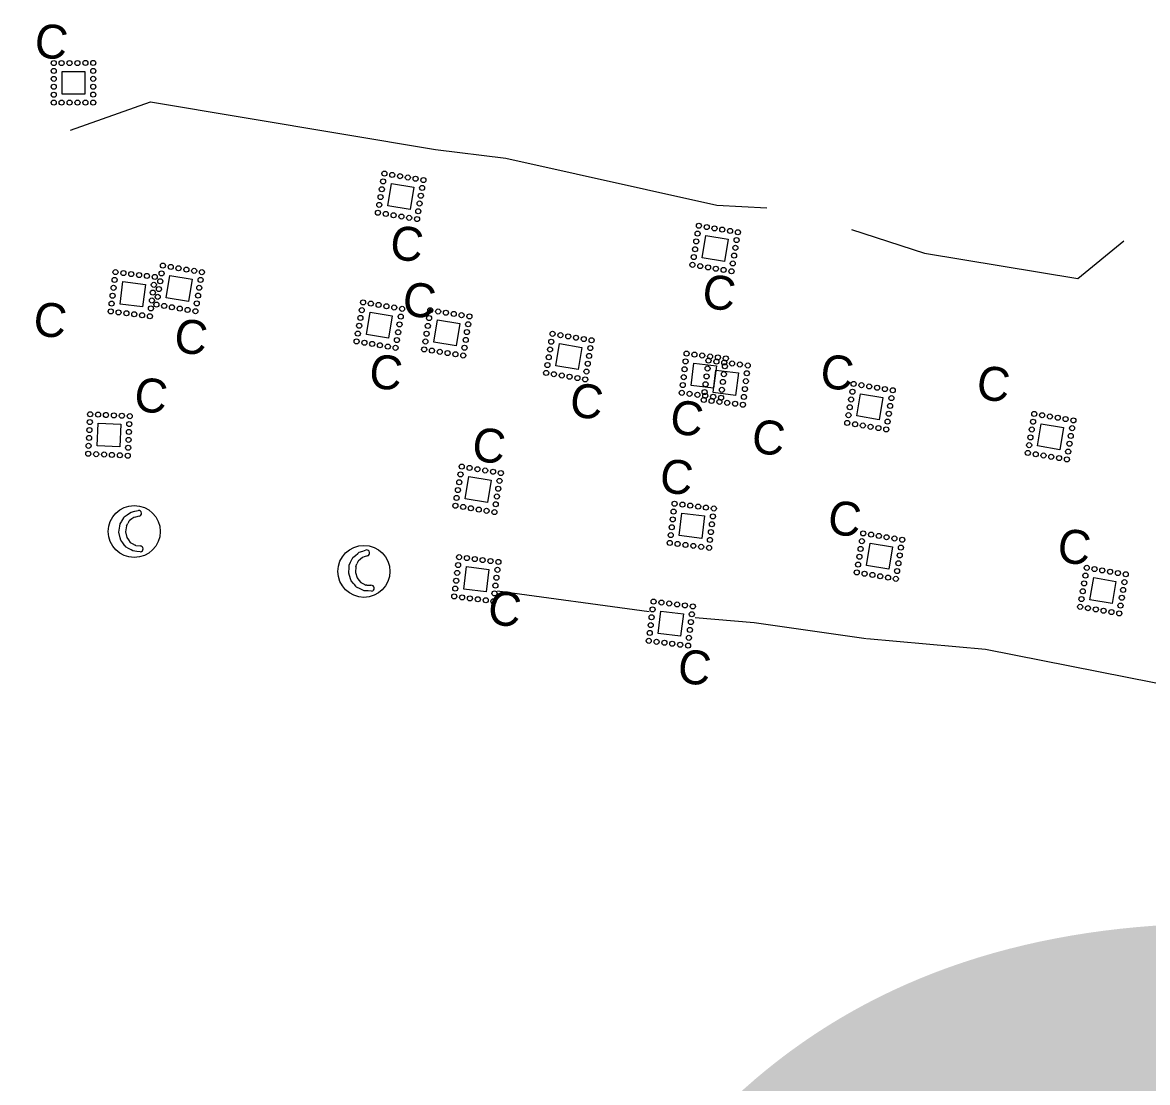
# Model space of a CAD drawing. Extents: x 2470000 to 2520000, y 340000 to 380000.
# Drawn here: x 2483983.6 to 2484481.2, y 365444.5 to 365913.2 of the extents above; entities that cross this region are included whole.
import ezdxf

# ---------------------------------------------------------------- set-up
doc = ezdxf.new("R2010")
doc.units = 0
for name, color, linetype in [('Coir Fiber Wattle with PAM Both CELL', 7, 'Continuous'), ('Prop Guardrail', 7, 'Continuous'), ('Prop Guardrail Anchor Unit CELL', 7, 'Continuous'), ('Prop Structure Anchor Unit CELL', 7, 'Continuous'), ('Rock Inlet Sediment Trap Type C CG CELL', 7, 'Continuous'), ('Scratch_Level_5', 7, 'Continuous'), ('Scratch_Level_6', 7, 'Continuous'), ('Sheet Data Field CELL', 7, 'Continuous')]:
    doc.layers.add(name, color=color, linetype=linetype)

# ---------------------------------------------------------------- blocks, each defined once
blk = doc.blocks.new('C3')
at = {"layer": 'Prop Guardrail'}
blk.add_text('C', height=0.3, dxfattribs=at).set_placement((-0.161, -0.136))
blk = doc.blocks.new('C2')
at = {"layer": 'Prop Guardrail Anchor Unit CELL'}
blk.add_text('C', height=0.3, dxfattribs=at).set_placement((-0.161, -0.136))

msp = doc.modelspace()

# ---------------------------------------------------------------- linework, layer by layer
at = {"layer": 'Coir Fiber Wattle with PAM Both CELL'}
for p, q in [((2484030.67, 365692.63), (2484030.13, 365691.66)), ((2484030.67, 365692.63), (2484030.79, 365692.84)), ((2484031.96, 365693.69), (2484030.79, 365692.84)), ((2484032.85, 365694.34), (2484031.96, 365693.69)), ((2484033.63, 365694.52), (2484032.85, 365694.34)), ((2484035.14, 365694.86), (2484033.63, 365694.52)), ((2484029.55, 365690.62), (2484029.21, 365688.01)), ((2484029.21, 365688), (2484029.21, 365688.01)), ((2484029.21, 365688), (2484029.75, 365685.52)), ((2484029.55, 365690.62), (2484030.13, 365691.66)), ((2484029.75, 365685.52), (2484030.43, 365684.53)), ((2484030.43, 365684.53), (2484031.25, 365683.33)), ((2484031.25, 365683.33), (2484032.13, 365682.82)), ((2484032.13, 365682.82), (2484033.41, 365682.07)), ((2484033.74, 365682.03), (2484033.41, 365682.07)), ((2484033.74, 365682.03), (2484035.58, 365681.76)), ((2484136.19, 365677.38), (2484134.71, 365676.91)), ((2484130.96, 365672.7), (2484130.83, 365670.08)), ((2484130.96, 365672.7), (2484131.46, 365673.79)), ((2484131.92, 365674.8), (2484131.46, 365673.79)), ((2484131.92, 365674.8), (2484132.02, 365675.01)), ((2484133.12, 365675.96), (2484132.02, 365675.01)), ((2484133.96, 365676.67), (2484133.12, 365675.96)), ((2484134.71, 365676.91), (2484133.96, 365676.67)), ((2484130.83, 365670.07), (2484130.83, 365670.08)), ((2484130.83, 365670.07), (2484131.57, 365667.63)), ((2484131.57, 365667.63), (2484132.32, 365666.7)), ((2484132.32, 365666.7), (2484133.24, 365665.58)), ((2484133.24, 365665.58), (2484134.16, 365665.13)), ((2484134.16, 365665.13), (2484135.5, 365664.49)), ((2484135.83, 365664.47), (2484135.5, 365664.49)), ((2484135.83, 365664.47), (2484137.69, 365664.36))]:
    msp.add_line(p, q, dxfattribs=at)
for points in [[(2484035.7, 365679.17), (2484034.16, 365679.37), (2484032.35, 365679.6), (2484031.63, 365680.01), (2484030.75, 365680.52), (2484029.2, 365681.42), (2484029.18, 365681.45), (2484028.92, 365681.81), (2484028.87, 365681.87), (2484028.31, 365682.64), (2484027.93, 365683.18), (2484027.07, 365684.37), (2484026.83, 365685.39), (2484026.24, 365687.87), (2484026.24, 365687.88), (2484026.61, 365690.49), (2484026.76, 365691.51), (2484027.34, 365692.48), (2484027.46, 365692.68), (2484027.96, 365693.51), (2484028.33, 365694.13), (2484028.42, 365694.28), (2484028.61, 365694.6), (2484028.62, 365694.6), (2484029.85, 365695.48), (2484030.94, 365696.25), (2484031.6, 365696.72), (2484033.31, 365697.14), (2484034.81, 365697.5)], [(2484138.01, 365661.78), (2484136.46, 365661.85), (2484134.64, 365661.94), (2484133.88, 365662.3), (2484132.97, 365662.73), (2484131.35, 365663.5), (2484131.32, 365663.53), (2484131.04, 365663.87), (2484130.99, 365663.92), (2484130.37, 365664.65), (2484129.94, 365665.16), (2484128.99, 365666.28), (2484128.67, 365667.27), (2484127.88, 365669.69), (2484127.88, 365669.7), (2484128.05, 365672.34), (2484128.11, 365673.36), (2484128.61, 365674.38), (2484128.72, 365674.59), (2484129.14, 365675.45), (2484129.47, 365676.11), (2484129.55, 365676.26), (2484129.71, 365676.59), (2484129.71, 365676.6), (2484130.87, 365677.57), (2484131.9, 365678.43), (2484132.52, 365678.95), (2484134.19, 365679.5), (2484135.66, 365679.98)]]:
    msp.add_lwpolyline(points, dxfattribs=at)
for centre in [(2484033, 365688.16), (2484134.6, 365670.53)]:
    msp.add_circle(centre, 11.5, dxfattribs=at)
for centre, radius, start, end in [((2484034.88, 365696.17), 1.33, 281.499, 92.6117), ((2484035.64, 365680.47), 1.3, 272.6117, 92.6117), ((2484135.83, 365678.66), 1.33, 286.0906, 97.2032), ((2484137.85, 365663.07), 1.3, 277.2032, 97.2032)]:
    msp.add_arc(centre, radius, start, end, dxfattribs=at)
at = {"layer": 'Prop Structure Anchor Unit CELL'}
for points in [[(2484027.99, 365798.65), (2484037.92, 365797.43), (2484036.7, 365787.51), (2484026.78, 365788.74)], [(2484017.09, 365736.07), (2484027.08, 365735.58), (2484026.59, 365725.59), (2484016.6, 365726.09)], [(2484275.29, 365696.25), (2484285.21, 365695.03), (2484284, 365685.1), (2484274.07, 365686.34)], [(2484358.55, 365683.01), (2484368.42, 365681.38), (2484366.79, 365671.52), (2484356.92, 365673.16)], [(2484179.96, 365672.61), (2484189.89, 365671.39), (2484188.67, 365661.46), (2484178.75, 365662.69)], [(2484457.39, 365667.76), (2484467.26, 365666.11), (2484465.61, 365656.25), (2484455.75, 365657.9)], [(2484265.99, 365652.97), (2484275.92, 365651.75), (2484274.7, 365641.83), (2484264.77, 365643.06)]]:
    msp.add_lwpolyline(points, close=True, dxfattribs=at)
for centre in [(2484024.72, 365802.85), (2484028.2, 365802.42), (2484031.67, 365802), (2484035.14, 365801.57), (2484038.62, 365801.14), (2484042.09, 365800.72), (2484023.87, 365795.9), (2484024.3, 365799.38), (2484041.67, 365797.24), (2484023.44, 365792.43), (2484041.24, 365793.77), (2484023.02, 365788.95), (2484040.39, 365786.82), (2484040.81, 365790.29), (2484022.59, 365785.48), (2484026.06, 365785.05), (2484029.54, 365784.63), (2484033.01, 365784.2), (2484036.48, 365783.77), (2484039.96, 365783.35), (2484013.35, 365736.52), (2484013.52, 365740.01), (2484017.02, 365739.84), (2484020.51, 365739.67), (2484024.01, 365739.5), (2484027.51, 365739.33), (2484031, 365739.16), (2484013.18, 365733.02), (2484030.66, 365732.16), (2484030.83, 365735.66), (2484012.84, 365726.03), (2484013.01, 365729.53), (2484030.49, 365728.67), (2484012.66, 365722.53), (2484016.16, 365722.36), (2484019.66, 365722.19), (2484023.15, 365722.02), (2484026.65, 365721.85), (2484030.14, 365721.68), (2484030.32, 365725.17), (2484271.59, 365696.97), (2484272.02, 365700.45), (2484275.49, 365700.02), (2484278.97, 365699.59), (2484282.44, 365699.17), (2484285.91, 365698.74), (2484289.39, 365698.31), (2484271.17, 365693.5), (2484288.54, 365691.37), (2484288.96, 365694.84), (2484270.31, 365686.55), (2484270.74, 365690.03), (2484288.11, 365687.89), (2484355.45, 365687.34), (2484358.91, 365686.77), (2484362.36, 365686.2), (2484269.89, 365683.08), (2484273.36, 365682.65), (2484276.83, 365682.22), (2484280.31, 365681.8), (2484283.78, 365681.37), (2484287.68, 365684.42), (2484354.88, 365683.89), (2484365.81, 365685.63), (2484369.27, 365685.06), (2484372.72, 365684.49), (2484176.69, 365676.81), (2484180.17, 365676.38), (2484287.26, 365680.94), (2484353.75, 365676.98), (2484354.31, 365680.43), (2484371.58, 365677.59), (2484372.15, 365681.04), (2484176.27, 365673.33), (2484183.64, 365675.95), (2484187.12, 365675.52), (2484190.59, 365675.1), (2484194.06, 365674.67), (2484353.18, 365673.53), (2484371.01, 365674.13), (2484454.31, 365672.09), (2484457.76, 365671.52), (2484175.41, 365666.38), (2484175.84, 365669.86), (2484193.21, 365667.72), (2484193.64, 365671.2), (2484352.61, 365670.07), (2484356.06, 365669.5), (2484359.51, 365668.93), (2484362.97, 365668.36), (2484366.42, 365667.79), (2484369.87, 365667.23), (2484370.44, 365670.68), (2484453.73, 365668.64), (2484461.21, 365670.94), (2484464.66, 365670.37), (2484468.12, 365669.79), (2484471.57, 365669.22), (2484174.99, 365662.91), (2484192.78, 365664.25), (2484452.58, 365661.73), (2484453.16, 365665.19), (2484470.42, 365662.31), (2484470.99, 365665.76), (2484174.56, 365659.44), (2484178.04, 365659.01), (2484181.51, 365658.58), (2484184.98, 365658.16), (2484188.46, 365657.73), (2484191.93, 365657.3), (2484192.36, 365660.78), (2484262.72, 365657.17), (2484266.19, 365656.74), (2484269.67, 365656.32), (2484452.01, 365658.28), (2484469.84, 365658.86), (2484262.29, 365653.69), (2484273.14, 365655.89), (2484276.62, 365655.46), (2484279.66, 365651.56), (2484280.09, 365655.04), (2484451.43, 365654.83), (2484454.88, 365654.25), (2484458.34, 365653.68), (2484461.79, 365653.1), (2484465.24, 365652.53), (2484468.69, 365651.95), (2484469.27, 365655.41), (2484261.44, 365646.75), (2484261.87, 365650.22), (2484279.24, 365648.09), (2484261.01, 365643.27), (2484278.81, 365644.61), (2484260.59, 365639.8), (2484264.06, 365639.37), (2484267.53, 365638.95), (2484271.01, 365638.52), (2484274.48, 365638.09), (2484277.96, 365637.67), (2484278.38, 365641.14)]:
    msp.add_circle(centre, 1.12, dxfattribs=at)
at = {"layer": 'Scratch_Level_5'}
for points in [[(2484001.14, 365891.55), (2484011.14, 365891.56), (2484011.15, 365881.56), (2484001.15, 365881.56)], [(2484146.75, 365842.08), (2484156.62, 365840.45), (2484154.99, 365830.58), (2484145.13, 365832.22)], [(2484285.85, 365819.01), (2484295.72, 365817.38), (2484294.09, 365807.52), (2484284.23, 365809.16)], [(2484048.77, 365801.39), (2484058.64, 365799.73), (2484056.98, 365789.87), (2484047.12, 365791.54)], [(2484137.29, 365785.15), (2484147.16, 365783.52), (2484145.53, 365773.65), (2484135.67, 365775.29)], [(2484167.09, 365781.68), (2484176.97, 365780.12), (2484175.42, 365770.25), (2484165.54, 365771.81)], [(2484221.15, 365771.22), (2484231.01, 365769.59), (2484229.39, 365759.73), (2484219.52, 365761.36)], [(2484280.59, 365762.63), (2484290.51, 365761.41), (2484289.29, 365751.48), (2484279.37, 365752.71)], [(2484290.3, 365759.51), (2484300.23, 365758.29), (2484299.01, 365748.36), (2484289.08, 365749.59)], [(2484354.32, 365749.1), (2484364.19, 365747.47), (2484362.56, 365737.6), (2484352.7, 365739.24)], [(2484434.23, 365735.82), (2484444.09, 365734.2), (2484442.47, 365724.33), (2484432.6, 365725.97)], [(2484180.98, 365712.51), (2484190.85, 365710.88), (2484189.22, 365701.01), (2484179.36, 365702.65)]]:
    msp.add_lwpolyline(points, close=True, dxfattribs=at)
for centre in [(2483997.38, 365895.31), (2484000.88, 365895.32), (2484004.38, 365895.32), (2484007.88, 365895.32), (2484011.38, 365895.33), (2484014.88, 365895.33), (2483997.38, 365891.81), (2484014.88, 365891.83), (2483997.39, 365888.31), (2484014.89, 365888.33), (2483997.39, 365884.81), (2483997.39, 365881.31), (2484014.89, 365884.83), (2484014.89, 365881.33), (2483997.4, 365877.81), (2484000.9, 365877.82), (2484004.4, 365877.82), (2484007.9, 365877.82), (2484011.4, 365877.83), (2484014.9, 365877.83), (2484143.66, 365846.41), (2484147.11, 365845.84), (2484143.09, 365842.95), (2484150.56, 365845.27), (2484154.02, 365844.7), (2484157.47, 365844.13), (2484160.92, 365843.56), (2484141.95, 365836.04), (2484142.52, 365839.5), (2484159.78, 365836.65), (2484160.35, 365840.1), (2484141.38, 365832.59), (2484159.22, 365833.2), (2484140.81, 365829.14), (2484144.26, 365828.57), (2484147.72, 365828), (2484151.17, 365827.43), (2484154.62, 365826.86), (2484158.08, 365826.29), (2484158.65, 365829.74), (2484282.76, 365823.34), (2484286.21, 365822.77), (2484289.66, 365822.2), (2484293.12, 365821.63), (2484296.57, 365821.06), (2484281.62, 365816.43), (2484282.19, 365819.89), (2484299.45, 365817.04), (2484300.02, 365820.49), (2484281.05, 365812.98), (2484298.89, 365813.59), (2484045.69, 365805.73), (2484279.91, 365806.07), (2484280.48, 365809.53), (2484297.75, 365806.68), (2484298.32, 365810.13), (2484045.11, 365802.27), (2484049.14, 365805.15), (2484052.59, 365804.57), (2484056.05, 365803.99), (2484059.5, 365803.41), (2484062.95, 365802.83), (2484283.36, 365805.5), (2484286.82, 365804.93), (2484290.27, 365804.37), (2484293.72, 365803.8), (2484297.18, 365803.23), (2484044.53, 365798.82), (2484061.79, 365795.92), (2484062.37, 365799.38), (2484043.37, 365791.92), (2484043.95, 365795.37), (2484061.21, 365792.47), (2484042.79, 365788.47), (2484046.25, 365787.89), (2484049.7, 365787.31), (2484053.15, 365786.73), (2484056.6, 365786.15), (2484060.63, 365789.02), (2484133.63, 365786.02), (2484134.2, 365789.48), (2484137.65, 365788.91), (2484141.11, 365788.34), (2484144.56, 365787.77), (2484148.01, 365787.2), (2484151.47, 365786.63), (2484163.97, 365785.99), (2484060.05, 365785.57), (2484133.06, 365782.57), (2484150.9, 365783.18), (2484163.42, 365782.53), (2484167.43, 365785.44), (2484170.88, 365784.9), (2484174.34, 365784.35), (2484177.8, 365783.81), (2484181.26, 365783.26), (2484132.49, 365779.12), (2484149.76, 365776.27), (2484150.33, 365779.72), (2484162.88, 365779.07), (2484180.17, 365776.35), (2484180.71, 365779.81), (2484131.35, 365772.21), (2484131.92, 365775.66), (2484134.81, 365771.64), (2484138.26, 365771.07), (2484149.19, 365772.82), (2484161.79, 365772.16), (2484162.33, 365775.62), (2484179.62, 365772.89), (2484217.48, 365772.09), (2484218.05, 365775.55), (2484221.5, 365774.98), (2484224.96, 365774.41), (2484228.41, 365773.84), (2484231.86, 365773.27), (2484235.32, 365772.7), (2484141.71, 365770.5), (2484145.17, 365769.93), (2484148.62, 365769.36), (2484161.24, 365768.7), (2484164.7, 365768.16), (2484168.16, 365767.61), (2484171.62, 365767.07), (2484175.07, 365766.52), (2484178.53, 365765.98), (2484179.08, 365769.43), (2484216.91, 365768.64), (2484234.18, 365765.79), (2484234.75, 365769.25), (2484277.32, 365766.83), (2484280.79, 365766.4), (2484284.27, 365765.97), (2484215.77, 365761.73), (2484216.34, 365765.19), (2484233.61, 365762.34), (2484276.89, 365763.35), (2484287.03, 365763.71), (2484287.74, 365765.55), (2484290.5, 365763.28), (2484291.21, 365765.12), (2484293.98, 365762.85), (2484294.26, 365761.22), (2484294.69, 365764.69), (2484297.45, 365762.43), (2484300.93, 365762), (2484304.4, 365761.57), (2484215.2, 365758.28), (2484218.66, 365757.71), (2484222.11, 365757.14), (2484225.56, 365756.57), (2484229.02, 365756), (2484233.04, 365758.89), (2484276.04, 365756.4), (2484276.46, 365759.88), (2484286.18, 365756.76), (2484286.6, 365760.23), (2484293.83, 365757.74), (2484303.97, 365758.1), (2484232.47, 365755.43), (2484275.61, 365752.93), (2484285.75, 365753.28), (2484293.41, 365754.27), (2484303.12, 365751.15), (2484303.55, 365754.62), (2484351.23, 365753.43), (2484354.68, 365752.86), (2484358.13, 365752.29), (2484361.59, 365751.72), (2484365.04, 365751.15), (2484275.18, 365749.46), (2484278.66, 365749.03), (2484282.13, 365748.6), (2484284.9, 365746.34), (2484285.32, 365749.81), (2484285.61, 365748.18), (2484288.37, 365745.91), (2484289.08, 365747.75), (2484292.55, 365747.32), (2484292.98, 365750.8), (2484302.69, 365747.68), (2484350.09, 365746.52), (2484350.66, 365749.97), (2484367.92, 365747.13), (2484368.49, 365750.58), (2484291.84, 365745.48), (2484295.32, 365745.06), (2484298.79, 365744.63), (2484302.27, 365744.2), (2484349.52, 365743.07), (2484367.35, 365743.67), (2484348.38, 365736.16), (2484348.95, 365739.61), (2484366.22, 365736.77), (2484366.78, 365740.22), (2484430.56, 365736.7), (2484431.13, 365740.15), (2484434.59, 365739.58), (2484438.04, 365739.01), (2484441.49, 365738.44), (2484444.95, 365737.88), (2484448.4, 365737.31), (2484351.83, 365735.59), (2484355.29, 365735.02), (2484358.74, 365734.45), (2484362.19, 365733.88), (2484365.65, 365733.31), (2484429.99, 365733.25), (2484447.83, 365733.85), (2484428.85, 365726.34), (2484429.42, 365729.79), (2484446.69, 365726.95), (2484447.26, 365730.4), (2484428.28, 365722.89), (2484431.74, 365722.32), (2484435.19, 365721.75), (2484438.65, 365721.18), (2484446.12, 365723.49), (2484177.89, 365716.84), (2484181.34, 365716.27), (2484442.1, 365720.61), (2484445.55, 365720.04), (2484177.32, 365713.38), (2484184.79, 365715.7), (2484188.25, 365715.13), (2484191.7, 365714.56), (2484195.15, 365713.99), (2484176.18, 365706.48), (2484176.75, 365709.93), (2484194.02, 365707.08), (2484194.58, 365710.54), (2484175.61, 365703.02), (2484193.45, 365703.63), (2484175.04, 365699.57), (2484178.49, 365699), (2484181.95, 365698.43), (2484185.4, 365697.86), (2484188.85, 365697.29), (2484192.31, 365696.72), (2484192.88, 365700.17)]:
    msp.add_circle(centre, 1.12, dxfattribs=at)
at = {"layer": 'Sheet Data Field CELL'}
for p, q in [((2484260.83, 365652.65), (2484193.65, 365661.76)), ((2484281.1, 365650.16), (2484307.16, 365647.87)), ((2484307.23, 365647.86), (2484356.75, 365640.88))]:
    msp.add_line(p, q, dxfattribs=at)
for points in [[(2484004.77, 365865.58), (2484040.26, 365878.2), (2484166.27, 365857.06)], [(2484166.27, 365857.06), (2484197.44, 365853.18), (2484290.76, 365832.48), (2484312.83, 365831.32)], [(2484350.33, 365821.74), (2484382.58, 365811.22), (2484450.41, 365800.05), (2484470.77, 365816.71)], [(2484357.04, 365640.85), (2484409.56, 365636.12), (2484584.1, 365601.56)]]:
    msp.add_lwpolyline(points, dxfattribs=at)

# ---------------------------------------------------------------- block references
at = {"layer": 'Prop Structure Anchor Unit CELL', "xscale": 50.00000000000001, "yscale": 49.99999999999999, "rotation": -6.997703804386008}
for p in [(2483996.58, 365780.92), (2484041.18, 365747.51)]:
    msp.add_blockref('C2', p, dxfattribs=at)
at = {"layer": 'Rock Inlet Sediment Trap Type C CG CELL', "xscale": 50.00000000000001, "yscale": 49.99999999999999, "rotation": -6.997703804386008}
for p in [(2484273.66, 365711.53), (2484348.03, 365693.07), (2484449.59, 365680.6), (2484197.65, 365653.21), (2484281.61, 365627.31)]:
    msp.add_blockref('C2', p, dxfattribs=at)
at = {"layer": 'Scratch_Level_5', "xscale": 49.99999999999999, "yscale": 50.00000000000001, "rotation": -6.997703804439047}
for p in [(2483997.09, 365904.02), (2484154.36, 365814.63), (2484292.48, 365792.99), (2484159.89, 365789.69), (2484058.86, 365773.43), (2484145.09, 365757.79), (2484344.68, 365757.73), (2484413.83, 365752.68), (2484233.89, 365745), (2484278.21, 365737.49), (2484314.34, 365728.95), (2484190.67, 365725.37)]:
    msp.add_blockref('C3', p, dxfattribs=at)

# ---------------------------------------------------------------- texts
at = {"layer": 'Scratch_Level_6'}
msp.add_text('4386', height=1000, dxfattribs=at).set_placement((2483403.76, 364500))

doc.saveas('drawing.dxf')
